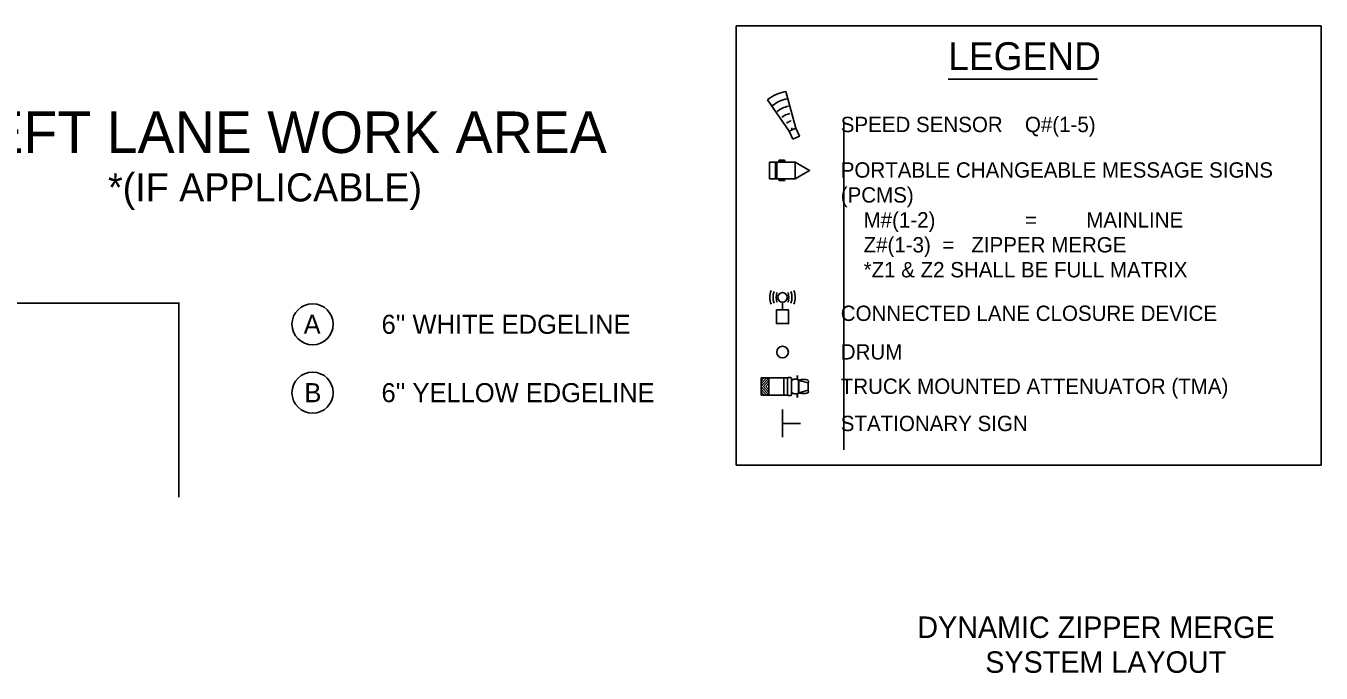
# Model space of a CAD drawing. Extents: x 1379436 to 1387057, y 792703 to 795604.
# Drawn here: x 1386121 to 1387026, y 794265 to 794717 of the extents above; entities that cross this region are included whole.
import ezdxf

# ---------------------------------------------------------------- set-up
doc = ezdxf.new("R2010")
doc.units = 0
for name, color, linetype in [('Black Area Fill Shapes', 7, 'Continuous'), ('Default', 7, 'Continuous'), ('Prop Mkg Solid White Lane Line', 7, 'Continuous'), ('Scratch_Level_0', 7, 'Continuous'), ('TCP Linework', 7, 'Continuous'), ('Text', 7, 'Continuous')]:
    doc.layers.add(name, color=color, linetype=linetype)

msp = doc.modelspace()

# ---------------------------------------------------------------- linework, layer by layer
at = {"layer": 'Black Area Fill Shapes'}
msp.add_lwpolyline([(1386656.59, 794638.08), (1386654.03, 794643.63), (1386658.78, 794645.82), (1386661.33, 794640.27)], close=True, dxfattribs=at)
at = {"layer": 'Default'}
for p, q in [((1384810.53, 794523.6), (1386228.13, 794523.6)), ((1386227.76, 794387.95), (1386227.76, 794523.6))]:
    msp.add_line(p, q, dxfattribs=at)
for centre in [(1386321.16, 794508.76), (1386321.16, 794460.95)]:
    msp.add_circle(centre, 14.37, dxfattribs=at)
at = {"layer": 'Prop Mkg Solid White Lane Line'}
for p, q in [((1386765.28, 794680), (1386869.48, 794680)), ((1386640.36, 794621.96), (1386640.36, 794610.41)), ((1386640.36, 794621.95), (1386658.23, 794621.95)), ((1386640.36, 794610.4), (1386640.36, 794621.95)), ((1386644.54, 794610.4), (1386644.54, 794621.95)), ((1386645.5, 794610.4), (1386645.5, 794621.95)), ((1386647.11, 794623.41), (1386650.8, 794623.41)), ((1386647.11, 794622.31), (1386650.8, 794622.31)), ((1386658.23, 794610.41), (1386658.23, 794621.95)), ((1386658.23, 794621.95), (1386668.22, 794616.18)), ((1386658.23, 794610.41), (1386668.22, 794616.18)), ((1386640.36, 794610.41), (1386658.23, 794610.41)), ((1386647.11, 794610.18), (1386650.8, 794610.18)), ((1386647.11, 794609.13), (1386650.8, 794609.13)), ((1386634.52, 794471.22), (1386652.97, 794471.22)), ((1386634.52, 794459.29), (1386634.52, 794471.22)), ((1386634.52, 794471.22), (1386634.52, 794468.95)), ((1386634.52, 794471.22), (1386634.52, 794468.95)), ((1386634.52, 794471.22), (1386634.52, 794468.95)), ((1386634.52, 794471.22), (1386634.52, 794468.95)), ((1386634.52, 794468.95), (1386634.52, 794471.22)), ((1386634.52, 794471.22), (1386636.55, 794471.22)), ((1386636.55, 794471.22), (1386634.52, 794468.95)), ((1386634.52, 794467.1), (1386638.21, 794471.22)), ((1386639.81, 794471.22), (1386634.52, 794465.26)), ((1386638.21, 794471.22), (1386639.81, 794471.22)), ((1386639.81, 794459.29), (1386639.81, 794471.22)), ((1386650.45, 794465.26), (1386650.45, 794471.22)), ((1386652.97, 794465.26), (1386652.97, 794471.22)), ((1386655.8, 794465.26), (1386655.8, 794471.22)), ((1386659.61, 794471.59), (1386659.61, 794473.07)), ((1386659.86, 794470.18), (1386659.86, 794473.07)), ((1386660.04, 794470.18), (1386660.04, 794473.07)), ((1386634.52, 794465.26), (1386634.52, 794467.1)), ((1386634.52, 794465.26), (1386639.81, 794459.29)), ((1386634.52, 794463.47), (1386634.52, 794465.26)), ((1386638.21, 794459.29), (1386634.52, 794463.47)), ((1386634.52, 794461.57), (1386634.52, 794459.29)), ((1386636.55, 794459.29), (1386634.52, 794461.57)), ((1386636.18, 794465.26), (1386639.81, 794469.38)), ((1386639.81, 794461.2), (1386636.18, 794465.26)), ((1386639.81, 794467.53), (1386637.78, 794465.26)), ((1386637.84, 794465.26), (1386639.81, 794463.04)), ((1386639.81, 794469.38), (1386639.81, 794467.53)), ((1386639.81, 794463.04), (1386639.81, 794461.2)), ((1386650.45, 794465.26), (1386650.45, 794459.29)), ((1386652.97, 794465.26), (1386652.97, 794459.29)), ((1386655.8, 794465.26), (1386655.8, 794459.29)), ((1386660.53, 794465.26), (1386660.53, 794469.56)), ((1386660.53, 794465.26), (1386660.53, 794460.95)), ((1386660.97, 794469.56), (1386667.42, 794467.78)), ((1386660.97, 794465.26), (1386660.97, 794469.56)), ((1386660.97, 794465.26), (1386660.97, 794460.95)), ((1386660.97, 794460.95), (1386667.42, 794462.74)), ((1386667.42, 794465.26), (1386667.42, 794467.78)), ((1386667.42, 794465.26), (1386667.42, 794462.74)), ((1386634.52, 794459.29), (1386652.97, 794459.29)), ((1386634.52, 794459.29), (1386636.55, 794459.29)), ((1386639.81, 794459.29), (1386638.21, 794459.29)), ((1386659.61, 794458.92), (1386659.61, 794457.51)), ((1386659.86, 794460.34), (1386659.86, 794457.51)), ((1386660.04, 794460.34), (1386660.04, 794457.51)), ((1386649.48, 794449.18), (1386649.48, 794429.91)), ((1386649.48, 794439.47), (1386661.96, 794439.47))]:
    msp.add_line(p, q, dxfattribs=at)
for centre, radius in [((1386668.32, 794616.17), 0.102), ((1386649.48, 794489.31), 4.08), ((1386649.48, 794489.31), 4.08)]:
    msp.add_circle(centre, radius, dxfattribs=at)
for centre, radius, start, end in [((1386647.78, 794622.84), 0.852, 142.08835, 217.91165), ((1386650.13, 794622.84), 0.852, 322.08835, 37.91165), ((1386647.78, 794609.65), 0.852, 142.08835, 217.91165), ((1386650.13, 794609.65), 0.852, 322.08835, 37.91165), ((1386665.83, 794468.64), 1.79, 331.88007, 28.11992), ((1386665.83, 794461.89), 1.79, 331.88007, 28.11993)]:
    msp.add_arc(centre, radius, start, end, dxfattribs=at)
for centre, major_axis, ratio, start_param, end_param in [((1386654.4, 794471.23), (1.41, 0), 0.269913, 6.283185, 9.424778), ((1386658.19, 794469.27), (2.37, 0.29), 0.503092, 0, 3.141593), ((1386658.19, 794461.26), (2.37, -0.29), 0.503092, 3.141593, 6.283185), ((1386664.18, 794469.53), (3.23, -0.04), 0.2034, 6.283185, 9.424778), ((1386654.4, 794459.3), (1.41, 0), 0.269913, 3.141593, 6.283185), ((1386664.18, 794461.01), (3.23, 0.04), 0.2034, 3.141593, 6.283185)]:
    msp.add_ellipse(centre, major_axis=major_axis, ratio=ratio, start_param=start_param, end_param=end_param, dxfattribs=at)
at = {"layer": 'Scratch_Level_0'}
msp.add_line((1386692.36, 794421.07), (1386692.36, 794650.57), dxfattribs=at)
at = {"layer": 'TCP Linework'}
msp.add_lwpolyline([(1386617.11, 794717.29), (1387025.74, 794717.29), (1387025.74, 794410.33), (1386617.11, 794410.33)], close=True, dxfattribs=at)
at = {"layer": 'Text'}
for p, q in [((1386658.78, 794645.82), (1386651.77, 794671.46)), ((1386654.03, 794643.63), (1386639.09, 794665.62)), ((1386649.47, 794518.76), (1386649.47, 794524.26))]:
    msp.add_line(p, q, dxfattribs=at)
msp.add_lwpolyline([(1386645.27, 794518.76), (1386653.69, 794518.76), (1386653.69, 794509.25), (1386645.27, 794509.25)], close=True, dxfattribs=at)
msp.add_circle((1386649.47, 794527.56), 3.3, dxfattribs=at)
for centre, radius, start, end in [((1386656.93, 794643.59), 28.34, 100.47314, 129.0092), ((1386656.93, 794643.59), 23.1, 100.47314, 129.0092), ((1386656.93, 794643.59), 17.85, 100.47314, 129.0092), ((1386656.93, 794643.59), 12.61, 100.47314, 129.0092), ((1386656.93, 794643.59), 7.36, 100.47314, 129.0092), ((1386656.93, 794643.59), 2.12, 100.47314, 129.0092), ((1386655.24, 794527.56), 14.57, 161.06571, 198.93429), ((1386655.24, 794527.56), 12.37, 161.06571, 198.93429), ((1386655.24, 794527.56), 10.17, 161.06571, 198.93429), ((1386643.7, 794527.56), 10.17, 341.06571, 18.93429), ((1386643.7, 794527.56), 12.37, 341.06571, 18.93429), ((1386643.7, 794527.56), 14.57, 341.06571, 18.93429)]:
    msp.add_arc(centre, radius, start, end, dxfattribs=at)

# ---------------------------------------------------------------- texts
at = {"layer": 'Default'}
for s, height, p in [('LEFT LANE WORK AREA', 29.0274, (1386071.66, 794628.45)), ('*(IF APPLICABLE)', 19.6754, (1386178.27, 794594.59)), ('DYNAMIC ZIPPER MERGE', 15, (1386743.66, 794289.57)), ('SYSTEM LAYOUT', 15, (1386791.14, 794265.2))]:
    msp.add_text(s, height=height, dxfattribs=at).set_placement(p)
at = {"layer": 'Prop Mkg Solid White Lane Line'}
msp.add_text('LEGEND', height=19.395, dxfattribs=at).set_placement((1386765.28, 794686.47))
at = {"layer": 'Text'}
for s, height, p in [('SPEED SENSOR', 10.7216, (1386690.16, 794643.05)), ('Q#(1-5)', 10.722, (1386818.82, 794643.05)), ('PORTABLE CHANGEABLE MESSAGE SIGNS ', 10.7216, (1386690.16, 794611.23)), ('(PCMS)', 10.722, (1386690.16, 794593.8)), ('    M#(1-2)', 10.7216, (1386690.16, 794576.38)), ('=', 10.72, (1386818.82, 794576.38)), ('MAINLINE', 10.722, (1386861.7, 794576.38)), ('    Z#(1-3)  =   ZIPPER MERGE', 10.7216, (1386690.16, 794558.96)), ('    *Z1 & Z2 SHALL BE FULL MATRIX    ', 10.7216, (1386690.16, 794541.54)), ('CONNECTED LANE CLOSURE DEVICE', 10.7216, (1386690.16, 794511.08)), ('A', 13.31, (1386314.94, 794502.11)), ("6'' WHITE EDGELINE", 13.31, (1386369.37, 794502.11)), ('DRUM', 10.722, (1386690.16, 794484.13)), ('TRUCK MOUNTED ATTENUATOR (TMA)', 10.7216, (1386690.16, 794460.09)), ('B', 13.31, (1386315.46, 794454.3)), ("6'' YELLOW EDGELINE", 13.31, (1386369.33, 794454.3)), ('STATIONARY SIGN', 10.7216, (1386690.16, 794434.11))]:
    msp.add_text(s, height=height, dxfattribs=at).set_placement(p)

doc.saveas('drawing.dxf')
